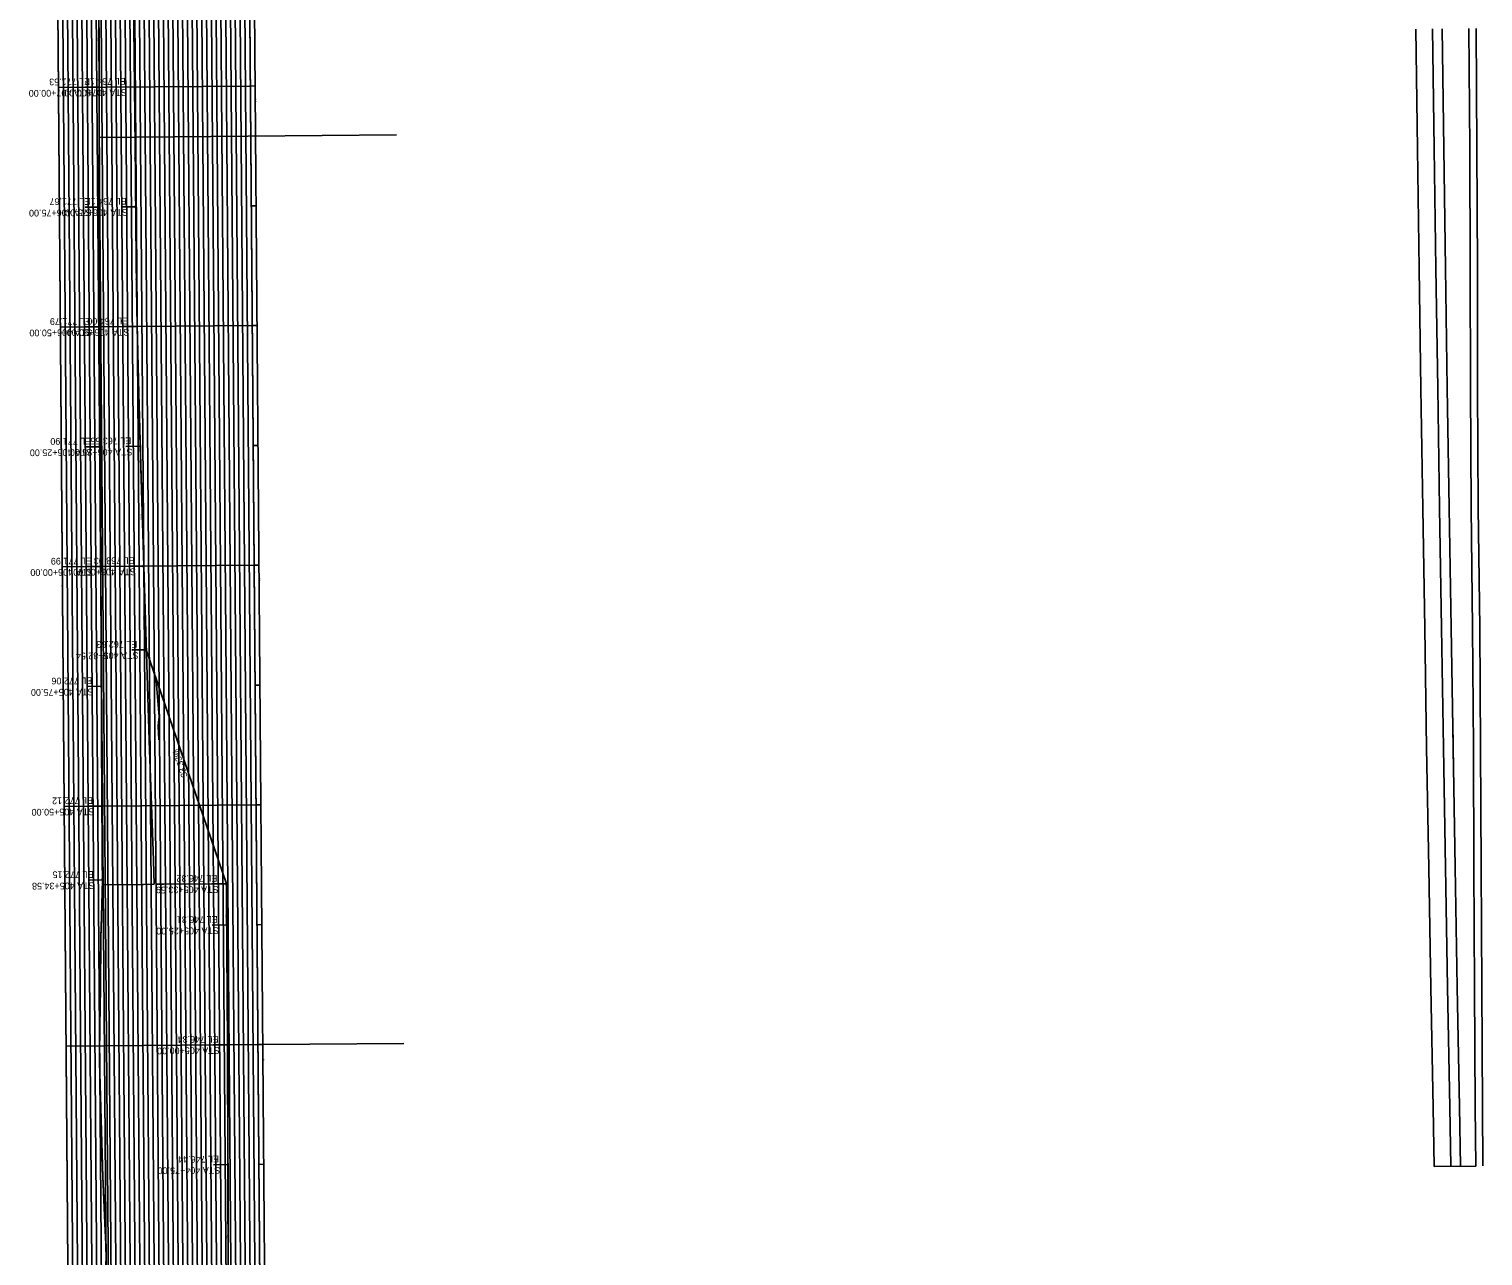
# Model space of a CAD drawing. Extents: x 592274 to 721355, y 141734 to 173089.
# Drawn here: x 593583.7 to 593886.9, y 172097.4 to 172353.4 of the extents above; entities that cross this region are included whole.
import ezdxf

# ---------------------------------------------------------------- set-up
doc = ezdxf.new("R2010")
doc.units = 0
for name, color, linetype in [('B_CONC', 7, 'Continuous'), ('B_CONC_LT', 7, 'Continuous'), ('B_GROUNDLINE', 7, 'Continuous'), ('B_MISC', 7, 'Continuous'), ('E_PROF_Grid', 7, 'Continuous'), ('E_PROF_GridMin', 7, 'Continuous'), ('P_E_PROF', 7, 'Continuous'), ('P_PROF', 7, 'Continuous'), ('P_PROF_Reference', 7, 'Continuous'), ('P_PROF_Text', 7, 'Continuous'), ('P_PROF_VPINotes', 7, 'Continuous')]:
    doc.layers.add(name, color=color, linetype=linetype)

msp = doc.modelspace()

# ---------------------------------------------------------------- linework, layer by layer
at = {"layer": 'B_CONC'}
for p, q in [((593872.91, 172353.39), (593873.25, 172328.39)), ((593878.41, 172353.46), (593878.75, 172328.47)), ((593873.25, 172328.39), (593873.6, 172303.39)), ((593878.75, 172328.47), (593879.1, 172303.47)), ((593873.6, 172303.39), (593873.97, 172278.39)), ((593879.1, 172303.47), (593879.46, 172278.47)), ((593873.97, 172278.39), (593874.35, 172253.39)), ((593879.46, 172278.47), (593879.85, 172253.48)), ((593874.35, 172253.39), (593874.75, 172228.39)), ((593879.85, 172253.48), (593880.25, 172228.48)), ((593874.75, 172228.39), (593875.16, 172203.39)), ((593880.25, 172228.48), (593880.66, 172203.48)), ((593875.16, 172203.39), (593875.59, 172178.39)), ((593880.66, 172203.49), (593881.09, 172178.49)), ((593875.59, 172178.39), (593876.04, 172153.39)), ((593881.09, 172178.49), (593881.54, 172153.49)), ((593876.04, 172153.39), (593876.5, 172128.39)), ((593881.54, 172153.49), (593882, 172128.5)), ((593876.5, 172128.39), (593876.73, 172116.09)), ((593882, 172128.5), (593882.23, 172116.14)), ((593876.73, 172116.09), (593885.4, 172116.16))]:
    msp.add_line(p, q, dxfattribs=at)
for points in [[(593876.41, 172353.44), (593876.75, 172328.44)], [(593876.75, 172328.44), (593877.1, 172303.44)], [(593877.1, 172303.44), (593877.47, 172278.44)], [(593877.47, 172278.44), (593877.85, 172253.45)], [(593877.85, 172253.45), (593878.25, 172228.45)], [(593878.25, 172228.45), (593878.66, 172203.45)], [(593878.66, 172203.45), (593879.09, 172178.45)], [(593879.09, 172178.45), (593879.54, 172153.46)], [(593879.54, 172153.46), (593880, 172128.46)], [(593880, 172128.46), (593880.23, 172116.12)]]:
    msp.add_lwpolyline(points, dxfattribs=at)
at = {"layer": 'B_CONC_LT'}
msp.add_line((593880.67, 172206.13), (593880.71, 172201.13), dxfattribs=at)
at = {"layer": 'B_GROUNDLINE'}
for points in [[(593883.97, 172353.5), (593884.15, 172328.5)], [(593884.15, 172328.5), (593884.25, 172303.5)], [(593884.25, 172303.5), (593884.28, 172278.5)], [(593884.28, 172278.5), (593884.43, 172253.5)], [(593884.43, 172253.5), (593884.73, 172228.5)], [(593884.73, 172228.5), (593884.91, 172203.5)], [(593884.91, 172203.5), (593885, 172178.5)], [(593885, 172178.5), (593885.15, 172153.5)], [(593885.15, 172153.5), (593885.28, 172128.5)], [(593885.28, 172128.5), (593885.4, 172116.16)]]:
    msp.add_lwpolyline(points, dxfattribs=at)
at = {"layer": 'B_MISC'}
for p, q in [((593885.47, 172353.51), (593885.65, 172328.51)), ((593598.32, 172330.8), (593660.34, 172331.3)), ((593598.32, 172330.8), (593603.79, 171641.29)), ((593885.65, 172328.5), (593885.75, 172303.5)), ((593885.75, 172303.5), (593885.78, 172278.5)), ((593885.78, 172278.51), (593885.93, 172253.51)), ((593885.93, 172253.52), (593886.23, 172228.52)), ((593886.23, 172228.51), (593886.41, 172203.51)), ((593886.41, 172203.51), (593886.5, 172178.51)), ((593886.5, 172178.51), (593886.65, 172153.51)), ((593886.65, 172153.51), (593886.78, 172128.51)), ((593632.41, 172141.53), (593661.84, 172141.76)), ((593886.78, 172128.52), (593886.9, 172116.18))]:
    msp.add_line(p, q, dxfattribs=at)
at = {"layer": 'E_PROF_Grid'}
msp.add_lwpolyline([(593636.37, 171641.54), (593629.11, 172558.84), (593628.11, 172558.83), (593635.37, 171641.54)], close=True, dxfattribs=at)
for points in [[(593595.38, 171641.22), (593588.25, 172541.19)], [(593605.37, 171641.3), (593598.25, 172541.27)], [(593615.37, 171641.38), (593608.24, 172541.35)], [(593625.37, 171641.46), (593618.24, 172541.43)], [(593635.37, 171641.54), (593628.24, 172541.51)], [(593629.83, 172341.51), (593589.83, 172341.2)], [(593630.83, 172341.52), (593629.83, 172341.51)], [(593630.83, 172341.52), (593629.83, 172341.51)], [(593630.83, 172341.52), (593629.83, 172341.51)], [(593630.62, 172241.52), (593590.62, 172241.2)], [(593631.62, 172241.53), (593630.62, 172241.52)], [(593631.62, 172241.53), (593630.62, 172241.52)], [(593631.62, 172241.53), (593630.62, 172241.52)], [(593631.41, 172141.52), (593591.41, 172141.2)], [(593632.41, 172141.53), (593631.41, 172141.52)], [(593632.41, 172141.53), (593631.41, 172141.52)], [(593632.41, 172141.53), (593631.41, 172141.52)]]:
    msp.add_lwpolyline(points, dxfattribs=at)
at = {"layer": 'E_PROF_GridMin'}
for points in [[(593596.38, 171641.23), (593589.25, 172541.2)], [(593597.37, 171641.24), (593590.25, 172541.21)], [(593598.37, 171641.24), (593591.25, 172541.22)], [(593599.37, 171641.25), (593592.25, 172541.22)], [(593600.37, 171641.26), (593593.25, 172541.23)], [(593601.37, 171641.27), (593594.25, 172541.24)], [(593602.37, 171641.28), (593595.25, 172541.25)], [(593603.37, 171641.28), (593596.25, 172541.26)], [(593604.37, 171641.29), (593597.25, 172541.26)], [(593606.37, 171641.31), (593599.25, 172541.28)], [(593607.37, 171641.32), (593600.25, 172541.29)], [(593608.37, 171641.32), (593601.25, 172541.29)], [(593609.37, 171641.33), (593602.25, 172541.3)], [(593610.37, 171641.34), (593603.25, 172541.31)], [(593611.37, 171641.35), (593604.25, 172541.32)], [(593612.37, 171641.35), (593605.24, 172541.33)], [(593613.37, 171641.36), (593606.24, 172541.33)], [(593614.37, 171641.37), (593607.24, 172541.34)], [(593616.37, 171641.39), (593609.24, 172541.36)], [(593617.37, 171641.39), (593610.24, 172541.37)], [(593618.37, 171641.4), (593611.24, 172541.37)], [(593619.37, 171641.41), (593612.24, 172541.38)], [(593620.37, 171641.42), (593613.24, 172541.39)], [(593621.37, 171641.43), (593614.24, 172541.4)], [(593622.37, 171641.43), (593615.24, 172541.41)], [(593623.37, 171641.44), (593616.24, 172541.41)], [(593624.37, 171641.45), (593617.24, 172541.42)], [(593626.37, 171641.47), (593619.24, 172541.44)], [(593627.37, 171641.47), (593620.24, 172541.45)], [(593628.37, 171641.48), (593621.24, 172541.45)], [(593629.37, 171641.49), (593622.24, 172541.46)], [(593630.37, 171641.5), (593623.24, 172541.47)], [(593631.37, 171641.51), (593624.24, 172541.48)], [(593632.37, 171641.51), (593625.24, 172541.48)], [(593633.37, 171641.52), (593626.24, 172541.49)], [(593634.37, 171641.53), (593627.24, 172541.5)], [(593631.03, 172316.52), (593630.03, 172316.52)], [(593630.22, 172291.52), (593590.23, 172291.2)], [(593631.22, 172291.52), (593630.22, 172291.52)], [(593631.42, 172266.53), (593630.42, 172266.52)], [(593631.82, 172216.53), (593630.82, 172216.52)], [(593631.02, 172191.52), (593591.02, 172191.2)], [(593632.02, 172191.53), (593631.02, 172191.52)], [(593632.21, 172166.53), (593631.21, 172166.52)], [(593632.61, 172116.53), (593631.61, 172116.52)]]:
    msp.add_lwpolyline(points, dxfattribs=at)
at = {"layer": 'P_E_PROF'}
for points in [[(593598.32, 172330.8), (593598.26, 172362.63)], [(593605.8, 172330.86), (593605.59, 172354.75)], [(593598.32, 172329.83), (593598.32, 172330.8)], [(593605.8, 172330.01), (593605.8, 172330.86)], [(593598.33, 172327.66), (593598.32, 172329.83)], [(593598.39, 172304.82), (593598.33, 172327.66)], [(593605.8, 172329.88), (593605.8, 172330.01)], [(593606.01, 172305.01), (593605.8, 172329.88)], [(593598.42, 172295.69), (593598.39, 172304.82)], [(593606.01, 172304.89), (593606.01, 172305.01)], [(593606.14, 172294.93), (593606.01, 172304.89)], [(593598.42, 172294.82), (593598.42, 172295.69)], [(593598.43, 172293.52), (593598.42, 172294.82)], [(593606.14, 172294.89), (593606.14, 172294.93)], [(593606.52, 172279.96), (593606.14, 172294.89)], [(593598.47, 172279.82), (593598.43, 172293.52)], [(593598.56, 172256.99), (593598.47, 172279.82)], [(593606.52, 172279.89), (593606.52, 172279.96)], [(593607.17, 172255.01), (593606.52, 172279.89)], [(593598.57, 172254.82), (593598.56, 172256.99)], [(593598.68, 172231.99), (593598.57, 172254.82)], [(593607.17, 172254.89), (593607.17, 172255.01)], [(593607.94, 172230), (593607.17, 172254.89)], [(593598.69, 172229.82), (593598.68, 172231.99)], [(593598.7, 172227.66), (593598.69, 172229.82)], [(593598.82, 172204.83), (593598.7, 172227.66)], [(593607.94, 172229.9), (593607.94, 172230)], [(593608.71, 172205), (593607.94, 172229.9)], [(593610.83, 172209.89), (593610.09, 172218.23)], [(593610.7, 172208.7), (593610.83, 172209.89)], [(593610.62, 172207.93), (593610.7, 172208.7)], [(593610.75, 172205.09), (593610.62, 172207.93)], [(593598.95, 172181.99), (593598.82, 172204.83)], [(593608.71, 172204.9), (593608.71, 172205)], [(593609.61, 172180), (593608.71, 172204.9)], [(593598.96, 172179.83), (593598.95, 172181.99)], [(593598.99, 172175.85), (593598.96, 172179.83)], [(593609.61, 172179.91), (593609.61, 172180)], [(593609.79, 172174.96), (593609.61, 172179.91)], [(593598.74, 172165.65), (593598.99, 172175.85)], [(593598.75, 172166.07), (593599.03, 172174.86)], [(593599.03, 172174.86), (593607.54, 172174.93)], [(593607.54, 172174.93), (593609.79, 172174.95)], [(593609.79, 172174.95), (593609.79, 172174.96)], [(593611.75, 172174.98), (593610.23, 172174.98)], [(593610.23, 172174.98), (593610.23, 172174.98)], [(593624.83, 172175.06), (593611.72, 172174.97)], [(593611.72, 172174.97), (593611.75, 172174.98)], [(593624.84, 172174), (593624.83, 172175.06)], [(593624.88, 172169.06), (593624.84, 172174)], [(593624.88, 172169.05), (593624.88, 172169.06)], [(593624.88, 172169), (593624.88, 172169.05)], [(593624.92, 172163.99), (593624.88, 172169)], [(593598.54, 172152.13), (593598.68, 172163.9)], [(593598.55, 172152.67), (593598.68, 172163.9)], [(593598.68, 172163.9), (593598.75, 172166.07)], [(593598.68, 172163.9), (593598.74, 172165.65)], [(593624.94, 172161.23), (593624.92, 172163.99)], [(593624.96, 172158.99), (593624.94, 172161.23)], [(593625, 172153.99), (593624.96, 172158.99)], [(593598.51, 172149.9), (593598.55, 172152.67)], [(593598.51, 172149.9), (593598.54, 172152.13)], [(593625.03, 172148.99), (593625, 172153.99)], [(593598.39, 172139.81), (593598.51, 172149.9)], [(593598.4, 172140.28), (593598.51, 172149.9)], [(593625.06, 172143.98), (593625.03, 172148.99)], [(593625.09, 172138.98), (593625.06, 172143.98)], [(593598.37, 172137.9), (593598.4, 172140.28)], [(593598.37, 172137.9), (593598.39, 172139.81)], [(593598.64, 172128.28), (593598.37, 172137.9)], [(593598.65, 172127.81), (593598.37, 172137.9)], [(593625.11, 172133.98), (593625.09, 172138.98)], [(593625.13, 172128.98), (593625.11, 172133.98)], [(593598.7, 172125.9), (593598.64, 172128.28)], [(593598.7, 172125.9), (593598.65, 172127.81)], [(593625.15, 172123.98), (593625.13, 172128.98)], [(593598.97, 172116.28), (593598.7, 172125.9)], [(593598.99, 172115.81), (593598.7, 172125.9)], [(593625.17, 172118.97), (593625.15, 172123.98)], [(593625.18, 172113.97), (593625.17, 172118.97)], [(593599.04, 172113.9), (593598.97, 172116.28)], [(593599.04, 172113.9), (593598.99, 172115.81)], [(593599.58, 172102.68), (593599.04, 172113.9)], [(593599.6, 172102.14), (593599.04, 172113.9)], [(593625.19, 172108.97), (593625.18, 172113.97)], [(593625.2, 172103.97), (593625.19, 172108.97)], [(593625.21, 172098.96), (593625.2, 172103.97)], [(593599.71, 172099.91), (593599.58, 172102.68)], [(593599.71, 172099.91), (593599.6, 172102.14)], [(593599.39, 172086.68), (593599.73, 172097.41)], [(593599.71, 172099.41), (593599.71, 172099.91)], [(593599.71, 172099.18), (593599.71, 172099.91)], [(593599.71, 172099.32), (593599.71, 172099.91)], [(593599.71, 172099.51), (593599.71, 172099.91)], [(593599.73, 172097.41), (593599.71, 172099.51)], [(593599.73, 172097.41), (593599.71, 172099.41)], [(593599.73, 172097.41), (593599.71, 172099.32)], [(593599.73, 172097.41), (593599.71, 172099.18)], [(593625.21, 172093.96), (593625.21, 172098.96)]]:
    msp.add_lwpolyline(points, dxfattribs=at)
at = {"layer": 'P_PROF'}
for points in [[(593598.3, 172341.27), (593598.26, 172366.27)], [(593605.7, 172341.32), (593605.41, 172366.32)], [(593598.36, 172316.26), (593598.3, 172341.27)], [(593605.92, 172316.32), (593605.7, 172341.32)], [(593598.43, 172291.26), (593598.36, 172316.26)], [(593606.23, 172291.33), (593605.92, 172316.32)], [(593598.53, 172266.26), (593598.43, 172291.26)], [(593606.87, 172266.33), (593606.23, 172291.33)], [(593598.63, 172241.26), (593598.53, 172266.26)], [(593607.59, 172241.34), (593606.87, 172266.33)], [(593598.76, 172216.26), (593598.63, 172241.26)], [(593608.13, 172223.88), (593607.59, 172241.34)], [(593624.83, 172175.06), (593608.13, 172223.88)], [(593598.9, 172191.27), (593598.76, 172216.26)], [(593598.99, 172175.85), (593598.9, 172191.27)], [(593624.9, 172166.47), (593624.83, 172175.06)], [(593625.07, 172141.47), (593624.9, 172166.47)], [(593625.17, 172116.47), (593625.07, 172141.47)], [(593625.21, 172091.47), (593625.17, 172116.47)]]:
    msp.add_lwpolyline(points, dxfattribs=at)
at = {"layer": 'P_PROF_Reference'}
for points in [[(593595.38, 171641.22), (593588.11, 172558.51)], [(593635.37, 171641.54), (593628.11, 172558.83)], [(593629.9, 172341.52), (593629.76, 172341.51)], [(593630.69, 172241.52), (593630.55, 172241.52)], [(593631.48, 172141.52), (593631.34, 172141.52)]]:
    msp.add_lwpolyline(points, dxfattribs=at)
at = {"layer": 'P_PROF_VPINotes'}
for points in [[(593598.3, 172341.27), (593595.3, 172341.24)], [(593605.7, 172341.32), (593602.7, 172341.3)], [(593598.36, 172316.26), (593595.36, 172316.24)], [(593605.92, 172316.32), (593602.92, 172316.3)], [(593598.43, 172291.26), (593595.43, 172291.24)], [(593606.23, 172291.33), (593603.23, 172291.3)], [(593598.53, 172266.26), (593595.53, 172266.24)], [(593606.87, 172266.33), (593603.87, 172266.31)], [(593598.63, 172241.26), (593595.63, 172241.24)], [(593607.59, 172241.34), (593604.59, 172241.31)], [(593608.13, 172223.88), (593605.13, 172223.86)], [(593598.76, 172216.26), (593595.76, 172216.24)], [(593598.9, 172191.27), (593595.9, 172191.24)], [(593598.99, 172175.85), (593595.99, 172175.82)], [(593624.83, 172175.06), (593621.83, 172175.04)], [(593624.9, 172166.47), (593621.9, 172166.45)], [(593625.07, 172141.47), (593622.07, 172141.45)], [(593625.17, 172116.47), (593622.17, 172116.45)]]:
    msp.add_lwpolyline(points, dxfattribs=at)
for centre in [(593598.3, 172341.27), (593605.7, 172341.32), (593598.36, 172316.26), (593605.92, 172316.32), (593598.43, 172291.26), (593606.23, 172291.33), (593598.53, 172266.26), (593606.87, 172266.33), (593598.63, 172241.26), (593607.59, 172241.34), (593608.13, 172223.88), (593598.76, 172216.26), (593598.9, 172191.27), (593598.99, 172175.85), (593624.83, 172175.06), (593624.9, 172166.47), (593625.07, 172141.47), (593625.17, 172116.47)]:
    msp.add_ellipse(centre, major_axis=(-0.003, 0.35), ratio=0.1, dxfattribs=at)

# ---------------------------------------------------------------- texts
at = {"layer": 'P_PROF_Reference'}
for s, p in [('407', (593630.05, 172339.87)), ('407+00.00', (593589.8, 172336.48)), ('406', (593630.85, 172239.86)), ('406+00.00', (593590.59, 172236.48)), ('405', (593631.64, 172139.89)), ('405+00.00', (593591.38, 172136.49))]:
    msp.add_text(s, height=0.14, rotation=90.4539, dxfattribs=at).set_placement(p)
at = {"layer": 'P_PROF_Text'}
for s, p in [('407+00', (593631.17, 172338.2)), ('406+00', (593631.97, 172238.2)), ('405+00', (593632.76, 172138.2))]:
    msp.add_text(s, height=0.14, rotation=90.4539, dxfattribs=at).set_placement(p)
at = {"layer": 'P_PROF_VPINotes'}
for s, height, rotation, p in [('0.38%', 0.15, 90.6714, (593605.49, 172351.06)), ('-0.61%', 0.164, 90.1028, (593598.18, 172350.77)), ('EL 771.53', 1.4, 180.4539, (593596.42, 172343.12)), ('EL 764.12', 1.4, 180.4539, (593603.83, 172343.18)), ('STA 407+00.00', 1.4, 180.4539, (593596.67, 172340.78)), ('STA 407+00.00', 1.4, 180.4539, (593604.08, 172340.84)), ('-0.56%', 0.16, 90.1347, (593598.23, 172325.77)), ('0.06%', 0.14, 90.4877, (593605.73, 172326.09)), ('STA 406+75.00', 1.4, 180.4539, (593596.73, 172315.78)), ('EL 771.67', 1.4, 180.4539, (593596.49, 172318.12)), ('STA 406+75.00', 1.4, 180.4539, (593604.29, 172315.84)), ('EL 764.11', 1.4, 180.4539, (593604.04, 172318.18)), ('-0.49%', 0.156, 90.1715, (593598.3, 172300.76)), ('0.45%', 0.154, 90.7134, (593606, 172301.05)), ('EL 771.79', 1.4, 180.4539, (593596.56, 172293.12)), ('EL 764.00', 1.4, 180.4539, (593604.36, 172293.18)), ('STA 406+50.00', 1.4, 180.4539, (593596.81, 172290.78)), ('STA 406+50.00', 1.4, 180.4539, (593604.6, 172290.84)), ('-0.42%', 0.152, 90.2137, (593598.39, 172275.75)), ('1.79%', 0.282, 91.4771, (593606.52, 172275.9)), ('EL 771.90', 1.4, 180.4539, (593596.65, 172268.12)), ('EL 763.55', 1.4, 180.4539, (593605, 172268.19)), ('STA 406+25.00', 1.4, 180.4539, (593596.9, 172265.78)), ('STA 406+25.00', 1.4, 180.4539, (593605.25, 172265.84)), ('2.07%', 0.316, 91.6416, (593607.21, 172250.93)), ('-0.36%', 0.149, 90.2462, (593598.49, 172250.74)), ('EL 771.99', 1.4, 180.4539, (593596.76, 172243.12)), ('EL 763.03', 1.4, 180.4539, (593605.71, 172243.19)), ('STA 406+00.00', 1.4, 180.4539, (593597.01, 172240.78)), ('STA 406+00.00', 1.4, 180.4539, (593605.96, 172240.85)), ('2.28%', 0.34, 91.7613, (593607.84, 172229.69)), ('EL 762.63', 1.4, 180.4539, (593606.25, 172225.74)), ('-0.30%', 0.146, 90.2819, (593598.61, 172225.74)), ('STA 405+82.54', 1.4, 180.4539, (593606.5, 172223.39)), ('STA 405+75.00', 1.4, 180.4539, (593597.13, 172215.78)), ('EL 772.06', 1.4, 180.4539, (593596.88, 172218.12)), ('33.33%', 1.342, 108.8888, (593616.78, 172197.53)), ('-0.24%', 0.144, 90.3176, (593598.74, 172200.73)), ('EL 772.12', 1.4, 180.4539, (593597.02, 172193.13)), ('STA 405+50.00', 1.4, 180.4539, (593597.27, 172190.78)), ('-0.19%', 0.143, 90.3431, (593598.86, 172180.51)), ('EL 772.15', 1.4, 180.4539, (593597.11, 172177.7)), ('EL 746.32', 1.4, 180.4539, (593622.95, 172176.91)), ('STA 405+34.58', 1.4, 180.4539, (593597.36, 172175.36)), ('STA 405+33.59', 1.4, 180.4539, (593623.2, 172174.57)), ('EL 746.31', 1.4, 180.4539, (593623.03, 172168.32)), ('0.05%', 0.14, 90.4821, (593624.79, 172168.03)), ('STA 405+25.00', 1.4, 180.4539, (593623.28, 172165.98)), ('-0.12%', 0.141, 90.3846, (593624.9, 172150.92)), ('EL 746.34', 1.4, 180.4539, (593623.2, 172143.33)), ('STA 405+00.00', 1.4, 180.4539, (593623.44, 172140.98)), ('-0.38%', 0.15, 90.2361, (593625.03, 172125.95)), ('EL 746.44', 1.4, 180.4539, (593623.3, 172118.32)), ('STA 404+75.00', 1.4, 180.4539, (593623.55, 172115.98)), ('-0.64%', 0.166, 90.0877, (593625.09, 172100.98))]:
    msp.add_text(s, height=height, rotation=rotation, dxfattribs=at).set_placement(p)

doc.saveas('drawing.dxf')
